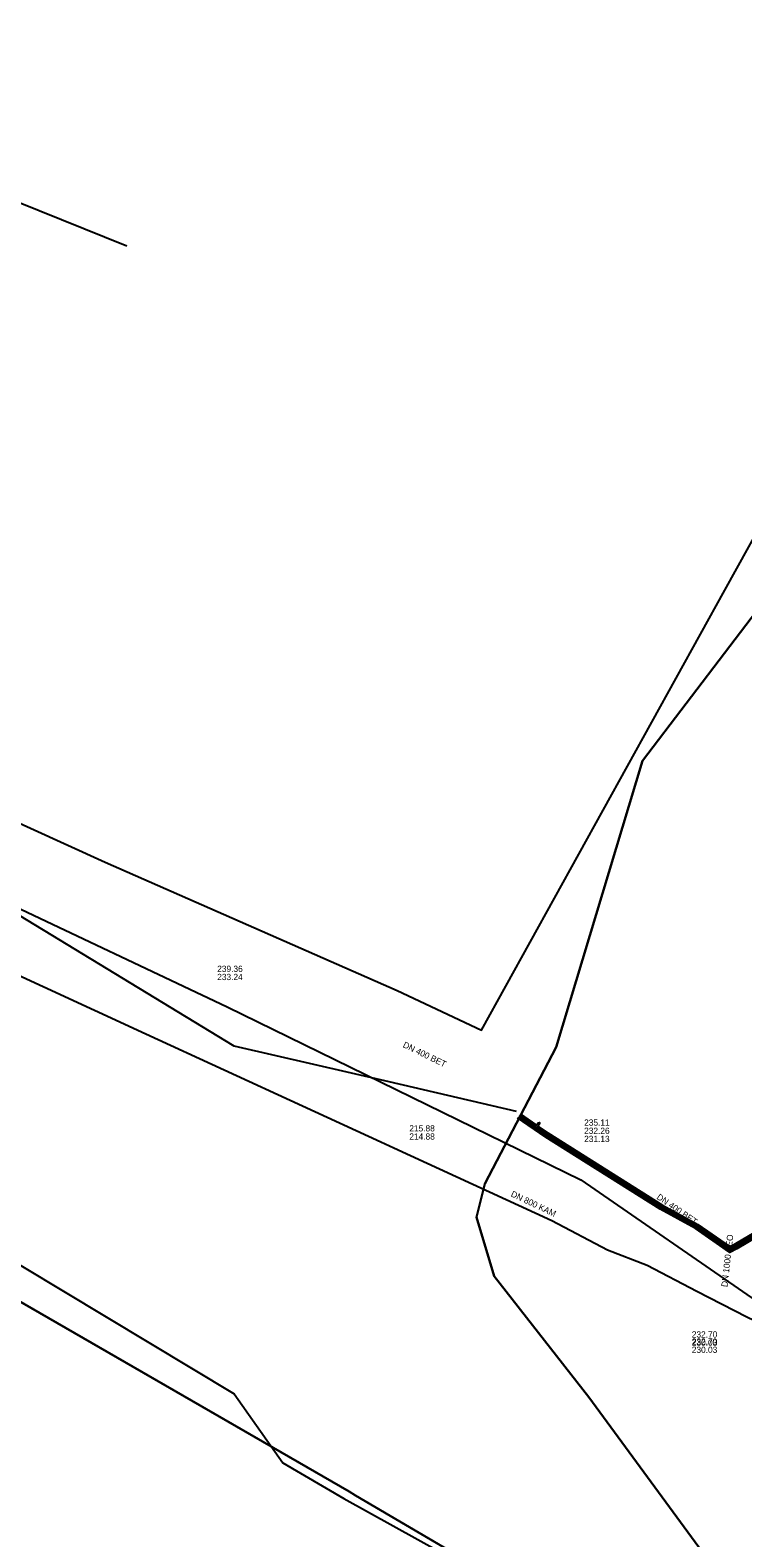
# Model space of a CAD drawing. Extents: x -598233 to -596890, y -1157848 to -1156431.
# Drawn here: x -597662.4 to -597570.9, y -1157384.6 to -1157191 of the extents above; entities that cross this region are included whole.
import ezdxf

# ---------------------------------------------------------------- set-up
doc = ezdxf.new("R2010")
doc.units = 0
for name, color, linetype in [('Vrstva 12', 7, 'Continuous'), ('Vrstva 13', 7, 'Continuous'), ('Vrstva 4', 7, 'Continuous'), ('Vrstva 42', 7, 'Continuous'), ('Vrstva 5', 7, 'Continuous'), ('Vrstva 52', 7, 'Continuous'), ('Vrstva 54', 7, 'Continuous'), ('Vrstva 58', 7, 'Continuous'), ('Vrstva 60', 7, 'Continuous'), ('Vrstva 8', 7, 'Continuous'), ('Vrstva 9', 7, 'Continuous')]:
    doc.layers.add(name, color=color, linetype=linetype)

msp = doc.modelspace()

# ---------------------------------------------------------------- linework, layer by layer
at = {"layer": 'Vrstva 13'}
for points in [[(-597573.24, -1157262.92), (-597554.76, -1157229.53), (-597509.71, -1157233.07), (-597508.66, -1157234.84), (-597505.66, -1157239.85), (-597500, -1157249.33)], [(-597615.34, -1157314.28), (-597604.49, -1157319.4), (-597573.24, -1157262.92)], [(-597685.45, -1157282.96), (-597652.8, -1157297.84), (-597615.34, -1157314.28)]]:
    msp.add_lwpolyline(points, dxfattribs=at)
at = {"layer": 'Vrstva 42'}
for points in [[(-597553.66, -1157342.53), (-597554.25, -1157340.32), (-597554.35, -1157340.35), (-597555.14, -1157340.61), (-597559.96, -1157341.87), (-597564.13, -1157342.95), (-597571.74, -1157347.44), (-597572.61, -1157347.92), (-597577.04, -1157344.87), (-597581.58, -1157342.37), (-597596.33, -1157333.09), (-597599.86, -1157330.63)], [(-597512.84, -1157386.48), (-597532.34, -1157370.31), (-597536.95, -1157366.73), (-597541.67, -1157362.38), (-597542.01, -1157362.06), (-597544.63, -1157359.64), (-597549.74, -1157353.01), (-597551.59, -1157350.19), (-597551.95, -1157348.93), (-597553.63, -1157343), (-597553.76, -1157342.56), (-597554.35, -1157340.35), (-597554.4, -1157340.16), (-597555.19, -1157340.42), (-597560.01, -1157341.68), (-597564.21, -1157342.76), (-597571.84, -1157347.27), (-597572.6, -1157347.69), (-597576.93, -1157344.7), (-597581.48, -1157342.2), (-597596.22, -1157332.92), (-597599.72, -1157330.48)], [(-597512.71, -1157386.32), (-597532.22, -1157370.15), (-597536.82, -1157366.57), (-597541.51, -1157362.25), (-597541.95, -1157361.85), (-597544.49, -1157359.5), (-597547.71, -1157355.32), (-597549.58, -1157352.89), (-597551.41, -1157350.11), (-597553.56, -1157342.5), (-597554.23, -1157340), (-597554.27, -1157339.9), (-597555.25, -1157340.22), (-597560.07, -1157341.48), (-597564.29, -1157342.58), (-597571.94, -1157347.09), (-597572.58, -1157347.45), (-597576.83, -1157344.52), (-597581.38, -1157342.02), (-597596.1, -1157332.76), (-597599.61, -1157330.32)], [(-597599.52, -1157330.14), (-597597.43, -1157331.59), (-597597.21, -1157331.27), (-597597.07, -1157331.24), (-597597.04, -1157331.39), (-597597.26, -1157331.71), (-597595.99, -1157332.59), (-597581.28, -1157341.85), (-597576.72, -1157344.35), (-597572.57, -1157347.22), (-597564.37, -1157342.39), (-597560.12, -1157341.29), (-597555.3, -1157340.03), (-597554.43, -1157339.75), (-597554.56, -1157339.35)]]:
    msp.add_lwpolyline(points, dxfattribs=at)
at = {"layer": 'Vrstva 5'}
for points in [[(-597714.78, -1157288.95), (-597687.73, -1157301.38), (-597647.6, -1157319.85), (-597617.43, -1157333.74), (-597615.76, -1157334.51)], [(-597615.76, -1157334.51), (-597595.45, -1157343.83), (-597588.31, -1157347.58), (-597583.21, -1157349.54), (-597576.85, -1157352.91), (-597570.44, -1157356.18), (-597556.91, -1157362.67)]]:
    msp.add_lwpolyline(points, dxfattribs=at)
at = {"layer": 'Vrstva 52'}
for points in [[(-597823.08, -1157218.29), (-597776.68, -1157239.7), (-597725.91, -1157263.01), (-597685.27, -1157291.61), (-597636.28, -1157321.38), (-597616.41, -1157325.99)], [(-597616.41, -1157325.99), (-597600.05, -1157329.78)]]:
    msp.add_lwpolyline(points, dxfattribs=at)
at = {"layer": 'Vrstva 54'}
for p, q in [((-597553.08, -1157244.43), (-597572.6, -1157270.07)), ((-597572.6, -1157270.07), (-597583.83, -1157284.82)), ((-597583.83, -1157284.82), (-597594.92, -1157321.55)), ((-597594.92, -1157321.55), (-597604.05, -1157339.11)), ((-597604.05, -1157339.11), (-597605.14, -1157343.41)), ((-597605.14, -1157343.41), (-597602.86, -1157350.98)), ((-597672.84, -1157349.01), (-597621.47, -1157378.62)), ((-597602.86, -1157350.98), (-597590.7, -1157366.5)), ((-597590.7, -1157366.5), (-597575.19, -1157387.68)), ((-597621.47, -1157378.62), (-597620.65, -1157379.11)), ((-597620.65, -1157379.11), (-597584.75, -1157400.18))]:
    msp.add_line(p, q, dxfattribs=at)
at = {"layer": 'Vrstva 58'}
msp.add_lwpolyline([(-597832.63, -1157258.59), (-597817.72, -1157263.35), (-597799.43, -1157271.54), (-597764.82, -1157287.79), (-597736.31, -1157305.25), (-597685.36, -1157336.53), (-597636.26, -1157366.06), (-597631.02, -1157373.49), (-597629.98, -1157374.94), (-597622.17, -1157379.53), (-597606.35, -1157388.28), (-597588.86, -1157398.94), (-597584.7, -1157401.36), (-597573.57, -1157409.91)], dxfattribs=at)
at = {"layer": 'Vrstva 60'}
for points in [[(-597452.46, -1157170.6), (-597474.26, -1157198.23), (-597496.65, -1157207.84), (-597524.08, -1157216.07), (-597544.75, -1157236.3), (-597553.08, -1157244.43), (-597572.6, -1157270.07), (-597583.83, -1157284.82), (-597594.92, -1157321.55), (-597604.05, -1157339.11), (-597605.14, -1157343.41), (-597602.86, -1157350.98), (-597590.7, -1157366.5), (-597575.19, -1157387.68)], [(-597575.19, -1157387.68), (-597590.7, -1157366.5), (-597602.86, -1157350.98), (-597605.14, -1157343.41), (-597604.05, -1157339.11), (-597594.92, -1157321.55), (-597583.83, -1157284.82), (-597572.6, -1157270.07), (-597553.08, -1157244.43), (-597544.75, -1157236.3), (-597524.08, -1157216.07), (-597496.65, -1157207.84), (-597474.26, -1157198.23), (-597452.46, -1157170.6)], [(-597672.84, -1157349.01), (-597621.47, -1157378.62), (-597620.65, -1157379.11), (-597584.75, -1157400.18)], [(-597584.75, -1157400.18), (-597620.65, -1157379.11), (-597621.47, -1157378.62), (-597672.84, -1157349.01)]]:
    msp.add_lwpolyline(points, dxfattribs=at)
at = {"layer": 'Vrstva 9'}
for p, q in [((-597650.01, -1157218.74), (-597672.26, -1157209.8)), ((-597682.45, -1157294.94), (-597637.13, -1157316.39)), ((-597637.13, -1157316.39), (-597591.74, -1157338.59)), ((-597591.74, -1157338.59), (-597569.21, -1157354.2))]:
    msp.add_line(p, q, dxfattribs=at)

# ---------------------------------------------------------------- texts
at = {"layer": 'Vrstva 12'}
for s, p in [('239.36', (-597638.42, -1157311.91)), ('233.24', (-597638.42, -1157312.96)), ('235.11', (-597591.32, -1157331.65)), ('232.26', (-597591.32, -1157332.7)), ('231.13', (-597591.32, -1157333.75)), ('232.70', (-597577.5, -1157358.85)), ('232.70', (-597577.5, -1157359.77)), ('230.03', (-597577.5, -1157359.9)), ('230.03', (-597577.5, -1157360.82))]:
    msp.add_text(s, height=0.8, dxfattribs=at).set_placement(p)
for rotation, p in [(333.9318, (-597614.66, -1157321.54)), (325.2698, (-597582.09, -1157340.99))]:
    msp.add_text('DN 400 BET', height=0.8, rotation=rotation, dxfattribs=at).set_placement(p)
at = {"layer": 'Vrstva 4'}
msp.add_text('DN 1000 BEO', height=0.8, rotation=83.4941, dxfattribs=at).set_placement((-597572.93, -1157352.4))
at = {"layer": 'Vrstva 8'}
for s, p in [('215.88', (-597613.76, -1157332.39)), ('214.88', (-597613.76, -1157333.44))]:
    msp.add_text(s, height=0.8, dxfattribs=at).set_placement(p)
msp.add_text('DN 800 KAM', height=0.8, rotation=334.4355, dxfattribs=at).set_placement((-597600.8, -1157340.69))

doc.saveas('drawing.dxf')
